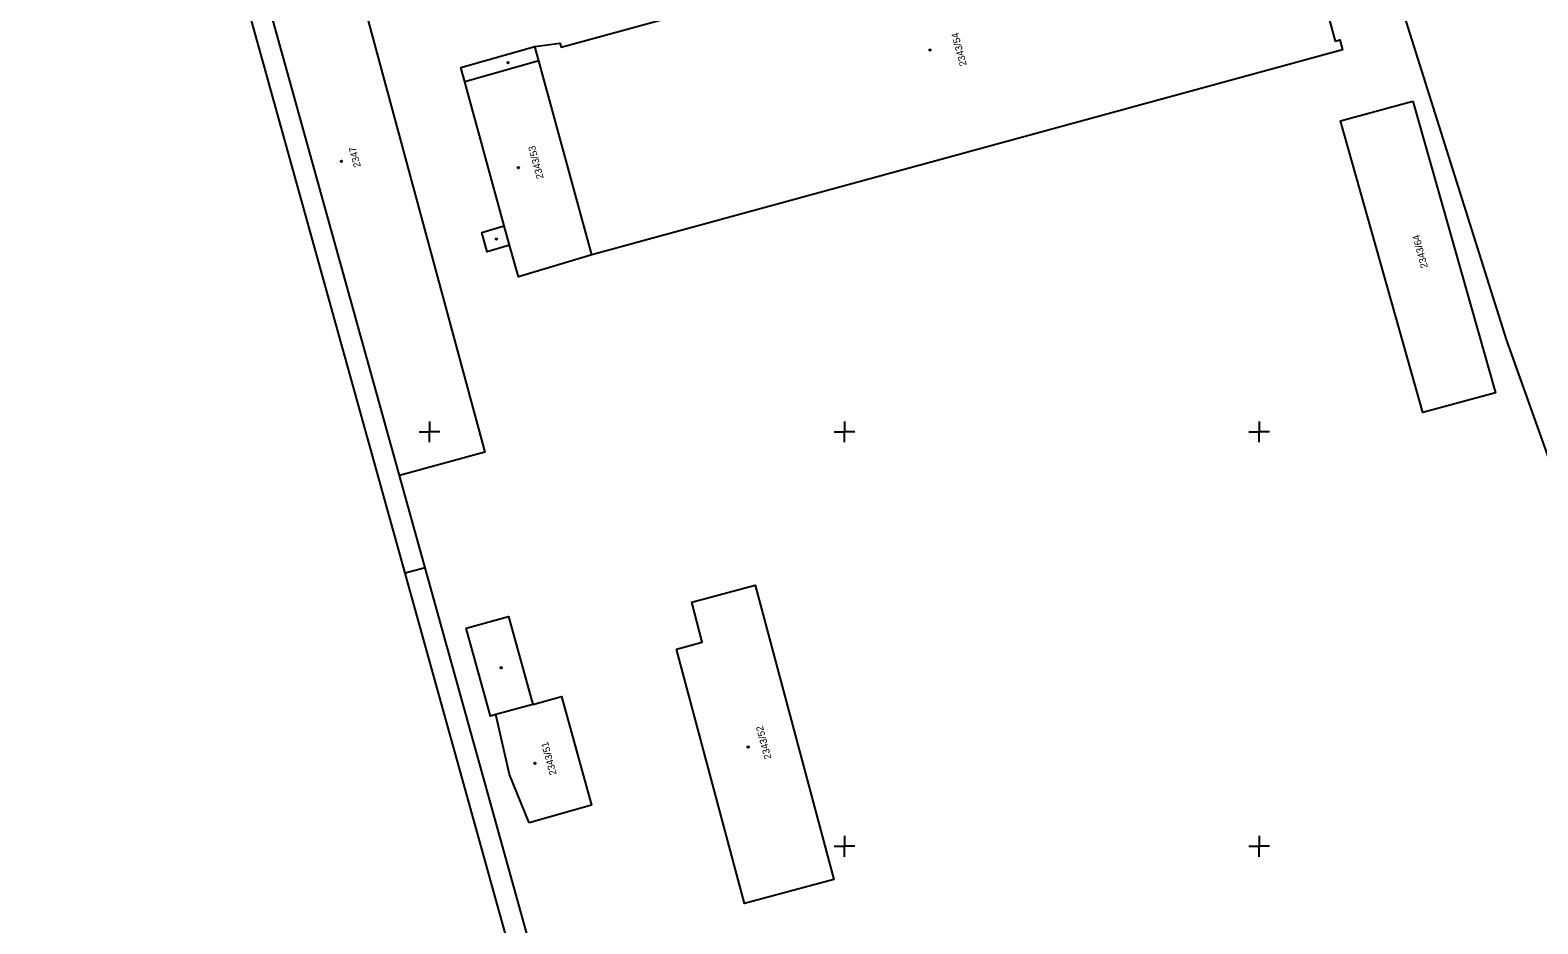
# Model space of a CAD drawing. Extents: x -821172 to -820632, y -1070921 to -1069931.
# Drawn here: x -821048.1 to -820866.4, y -1070659.4 to -1070551.6 of the extents above; entities that cross this region are included whole.
import ezdxf

# ---------------------------------------------------------------- set-up
doc = ezdxf.new("R2010")
doc.units = 0
for name, color, linetype in [('Ram', 7, 'Continuous'), ('Sit', 7, 'Continuous'), ('Vrstva 53', 7, 'Continuous'), ('Vrstva 55', 7, 'Continuous'), ('Vrstva 56', 7, 'Continuous'), ('Vrstva 57', 7, 'Continuous'), ('Vrstva 59', 7, 'Continuous')]:
    doc.layers.add(name, color=color, linetype=linetype)

msp = doc.modelspace()

# ---------------------------------------------------------------- linework, layer by layer
at = {"layer": 'Ram'}
msp.add_line((-821000.54, -1070616.4), (-821002.95, -1070617.07), dxfattribs=at)
for points in [[(-820775.54, -1070880.81), (-820918.62, -1070920.57), (-821143.51, -1070111.23)], [(-820916.88, -1070917.49), (-821140.43, -1070112.97)]]:
    msp.add_lwpolyline(points, dxfattribs=at)
at = {"layer": 'Sit'}
for p, q in [((-821000, -1070598.75), (-821000, -1070600)), ((-820950, -1070598.75), (-820950, -1070600)), ((-820900, -1070598.75), (-820900, -1070600)), ((-821001.25, -1070600), (-821000, -1070600)), ((-820998.75, -1070600), (-821000, -1070600)), ((-821000, -1070601.25), (-821000, -1070600)), ((-820951.25, -1070600), (-820950, -1070600)), ((-820948.75, -1070600), (-820950, -1070600)), ((-820950, -1070601.25), (-820950, -1070600)), ((-820901.25, -1070600), (-820900, -1070600)), ((-820898.75, -1070600), (-820900, -1070600)), ((-820900, -1070601.25), (-820900, -1070600)), ((-820951.25, -1070650), (-820950, -1070650)), ((-820950, -1070648.75), (-820950, -1070650)), ((-820948.75, -1070650), (-820950, -1070650)), ((-820950, -1070651.25), (-820950, -1070650)), ((-820901.25, -1070650), (-820900, -1070650)), ((-820900, -1070648.75), (-820900, -1070650)), ((-820898.75, -1070650), (-820900, -1070650)), ((-820900, -1070651.25), (-820900, -1070650))]:
    msp.add_line(p, q, dxfattribs=at)
at = {"layer": 'Vrstva 53'}
msp.add_lwpolyline([(-820793.34, -1070807.43), (-820797.89, -1070798.01), (-820802.49, -1070786.9), (-820807.86, -1070771.6), (-820839.34, -1070671.73), (-820847.49, -1070649.05), (-820862.12, -1070611.55), (-820870.18, -1070588.9), (-820893.88, -1070513.71), (-820901.78, -1070488.65), (-820908.48, -1070465.88), (-820912.77, -1070441.75), (-820907.91, -1070440.8), (-820914.43, -1070404.83), (-820920.34, -1070372.85), (-820926.76, -1070341.17), (-820933.59, -1070313.73), (-820939.94, -1070294.5), (-820946.33, -1070279.59), (-820953.63, -1070265.09), (-820959.73, -1070254.91)], dxfattribs=at)
at = {"layer": 'Vrstva 55'}
for points in [[(-820793.34, -1070807.43), (-820797.89, -1070798.01), (-820802.49, -1070786.9), (-820807.86, -1070771.6), (-820839.34, -1070671.73), (-820847.49, -1070649.05), (-820862.12, -1070611.55), (-820870.18, -1070588.9), (-820893.88, -1070513.71), (-820901.78, -1070488.65), (-820908.48, -1070465.88), (-820912.77, -1070441.75), (-820907.91, -1070440.8), (-820914.43, -1070404.83), (-820920.34, -1070372.85), (-820926.76, -1070341.17), (-820933.59, -1070313.73), (-820939.94, -1070294.5), (-820946.33, -1070279.59), (-820953.63, -1070265.09), (-820959.73, -1070254.91)], [(-821024.62, -1070529.75), (-821013.78, -1070526.79), (-820993.35, -1070602.46), (-821003.64, -1070605.27)], [(-820987.3, -1070553.53), (-820984.32, -1070553.15), (-820984.15, -1070553.64), (-820896.5, -1070529.65), (-820896.17, -1070530.88), (-820896.75, -1070531.03), (-820895.04, -1070537.38), (-820894.46, -1070537.22), (-820894.09, -1070538.61), (-820894.67, -1070538.77), (-820892.95, -1070545.12), (-820892.38, -1070544.96), (-820892, -1070546.35), (-820892.58, -1070546.51), (-820890.86, -1070552.89), (-820890.28, -1070552.73), (-820889.96, -1070553.93), (-820980.44, -1070578.68)], [(-820980.44, -1070578.68), (-820989.3, -1070581.34), (-820990.35, -1070577.5), (-820993.07, -1070578.31), (-820993.71, -1070575.96), (-820991.01, -1070575.17), (-820995.75, -1070557.79), (-820996.23, -1070556.06), (-820987.3, -1070553.53)], [(-820980.44, -1070578.68), (-820986.82, -1070555.27), (-820987.3, -1070553.53)], [(-820881.48, -1070560.15), (-820871.53, -1070595.32), (-820880.27, -1070597.68), (-820890.22, -1070562.51), (-820881.48, -1070560.15)], [(-820970.22, -1070626.22), (-820967.13, -1070625.39), (-820968.39, -1070620.55), (-820960.76, -1070618.51), (-820951.27, -1070654.01), (-820962.04, -1070656.89), (-820970.22, -1070626.22)], [(-820987.98, -1070647.18), (-820990.37, -1070641.34), (-820992.01, -1070634.12), (-820992.65, -1070634.3), (-820995.59, -1070623.7), (-820990.49, -1070622.29), (-820987.55, -1070632.89), (-820984.1, -1070631.93), (-820980.49, -1070645.05), (-820987.98, -1070647.18)]]:
    msp.add_lwpolyline(points, dxfattribs=at)
at = {"layer": 'Vrstva 56'}
for p, q in [((-820986.82, -1070555.27), (-820995.75, -1070557.79)), ((-820990.35, -1070577.5), (-820991.01, -1070575.17)), ((-820987.55, -1070632.89), (-820992.01, -1070634.12))]:
    msp.add_line(p, q, dxfattribs=at)
at = {"layer": 'Vrstva 59'}
for centre in [(-820990.53, -1070555.5), (-820939.69, -1070553.98), (-821010.62, -1070567.4), (-820989.3, -1070568.16), (-820991.94, -1070576.77), (-820991.37, -1070628.47), (-820961.6, -1070638.04), (-820987.31, -1070640)]:
    msp.add_circle(centre, 0.0875, dxfattribs=at)

# ---------------------------------------------------------------- texts
at = {"layer": 'Vrstva 57'}
for s, p in [('2343/54', (-820935.24, -1070555.78)), ('2347', (-821008.27, -1070568.01)), ('2343/53', (-820986.24, -1070569.4)), ('2343/64', (-820879.66, -1070580.15)), ('2343/52', (-820958.79, -1070639.37)), ('2343/51', (-820984.68, -1070641.29))]:
    msp.add_text(s, height=0.85, rotation=105, dxfattribs=at).set_placement(p)

doc.saveas('drawing.dxf')
